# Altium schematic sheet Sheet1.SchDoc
size A; SheetNumber: 1; SheetTotal: 1
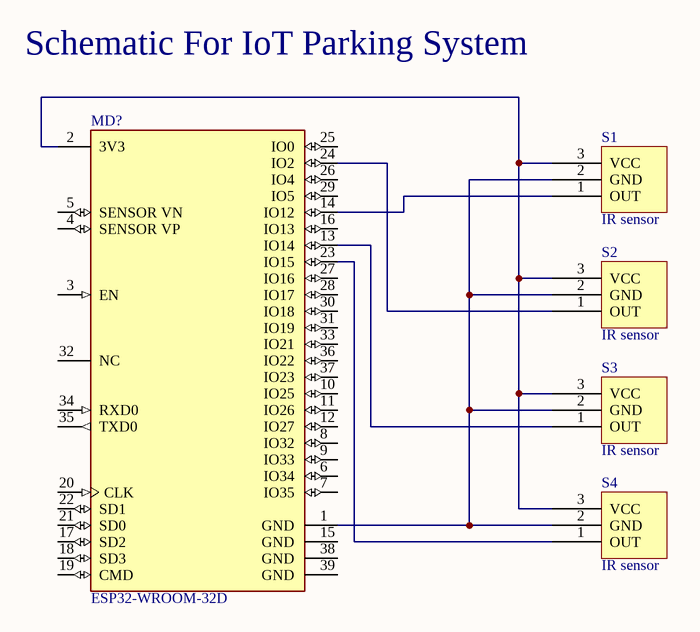
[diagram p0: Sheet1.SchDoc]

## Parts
MD?  ESP32-WROOM-32D  [FP-ESP32-WROOM-32D-MFG]
S1  IR sensor
S2  IR sensor
S3  IR sensor
S4  IR sensor

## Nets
NetMD?_1: MD?.1(GND) S1.2(GND) S2.2(GND) S3.2(GND) S4.2(GND)
NetMD?_2: MD?.2(3V3) S1.3(VCC) S2.3(VCC) S3.3(VCC) S4.3(VCC)
NetMD?_13: MD?.13(IO14) S3.1(OUT)
NetMD?_14: MD?.14(IO12) S1.1(OUT)
NetMD?_23: MD?.23(IO15) S4.1(OUT)
NetMD?_24: MD?.24(IO2) S2.1(OUT)

Not connected (* = marked no-connect by the designer): MD? 3(EN) 4(SENSOR_VP) 5(SENSOR_VN) 6(IO34) 7(IO35) 8(IO32) 9(IO33) 10(IO25) 11(IO26) 12(IO27) 15(GND) 16(IO13) 17(SD2) 18(SD3) 19(CMD) 20(CLK) 21(SD0) 22(SD1) 25(IO0) 26(IO4) 27(IO16) 28(IO17) 29(IO5) 30(IO18) 31(IO19) 32(NC) 33(IO21) 34(RXD0) 35(TXD0) 36(IO22) 37(IO23) 38(GND) 39(GND)

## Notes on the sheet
- Schematic For IoT Parking System

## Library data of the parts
MD? = CMP-194065-000003-1: WIFI MODULE 32MBITS SPI FLASH; Manufacturer: Espressif Systems; Max Supply Voltage: 3.6V; Nominal Supply Current: 500mA; Max Frequency: 2484MHz; Number Of Adc Channels: 16; Number Of Gpio: 32; Interface: I2C,SPI,UART,Ethernet,I2S,Other; Data Rate: 150Mbits/s; Min Supply Voltage: 3V; Bandwidth: 72MHz; Sensitivity: -98dBm
S1-S4 = Component_1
